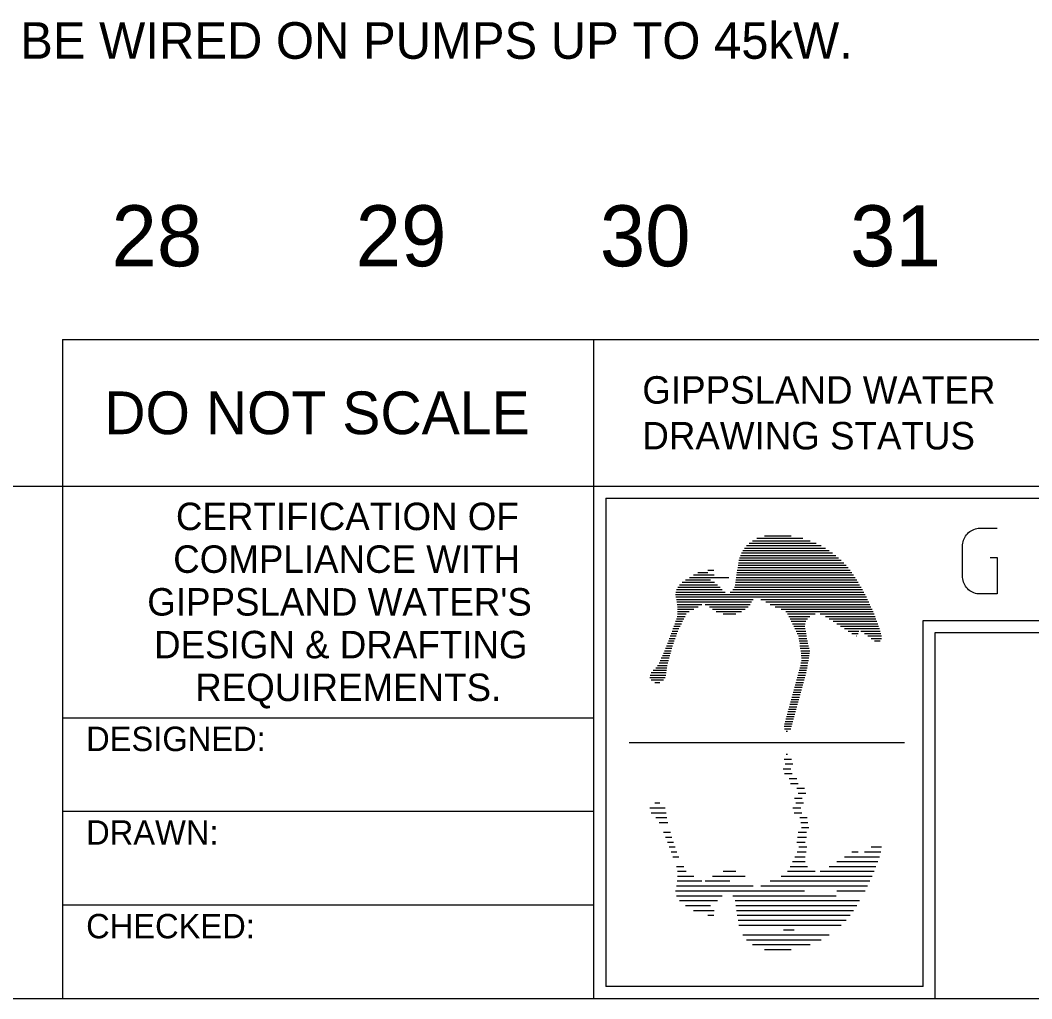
# Model space of a CAD drawing. Extents: x 0 to 841, y 0 to 594.
# Drawn here: x 589 to 671.9, y 15 to 95.2 of the extents above; entities that cross this region are included whole.
import ezdxf

# ---------------------------------------------------------------- set-up
doc = ezdxf.new("R2010")
doc.units = 0
doc.layers.add('A1BORDER', color=7, linetype='Continuous')
doc.layers.add('Level 1', color=7, linetype='Continuous')

msp = doc.modelspace()

# ---------------------------------------------------------------- linework, layer by layer
at = {"layer": 'A1BORDER'}
for p, q in [((592.5, 69), (592.5, 15)), ((592.5, 69), (829, 69)), ((636, 69), (636, 15)), ((28, 57), (829, 57)), ((637, 56), (788, 56)), ((637, 56), (637, 16)), ((648.74, 52.32), (654.24, 52.32)), ((649.02, 52.52), (653.76, 52.52)), ((649.39, 52.72), (653.15, 52.72)), ((650.01, 52.92), (652.2, 52.92)), ((648.12, 51.52), (655.59, 51.52)), ((648.23, 51.72), (655.31, 51.72)), ((648.37, 51.92), (655, 51.92)), ((648.53, 52.12), (654.64, 52.12)), ((647.88, 50.72), (656.5, 50.72)), ((647.91, 50.92), (656.3, 50.92)), ((647.96, 51.12), (656.08, 51.12)), ((648.03, 51.32), (655.85, 51.32)), ((644.18, 49.72), (645.89, 49.72)), ((644.54, 49.92), (645.36, 49.92)), ((645.37, 50.12), (645.86, 50.12)), ((647.71, 49.72), (657.31, 49.72)), ((647.75, 49.92), (657.17, 49.92)), ((647.78, 50.12), (657.02, 50.12)), ((647.81, 50.32), (656.86, 50.32)), ((647.85, 50.52), (656.69, 50.52)), ((643.04, 48.92), (646.16, 48.92)), ((643.26, 49.12), (645.9, 49.12)), ((643.54, 49.32), (645.57, 49.32)), ((643.85, 49.52), (647.09, 49.52)), ((647.61, 48.92), (657.8, 48.92)), ((647.63, 49.12), (657.68, 49.12)), ((647.66, 49.32), (657.57, 49.32)), ((647.69, 49.52), (657.44, 49.52)), ((642.73, 48.12), (658.25, 48.12)), ((642.75, 48.32), (646.79, 48.32)), ((642.81, 48.52), (646.55, 48.52)), ((642.9, 48.72), (646.37, 48.72)), ((647.19, 48.32), (658.14, 48.32)), ((647.42, 48.52), (658.03, 48.52)), ((647.54, 48.72), (657.92, 48.72)), ((642.74, 47.92), (658.35, 47.92)), ((642.79, 47.72), (649.08, 47.72)), ((642.83, 47.52), (648.95, 47.52)), ((642.85, 47.31), (644.88, 47.31)), ((645.14, 47.31), (648.83, 47.31)), ((649.72, 47.72), (658.45, 47.72)), ((650.12, 47.52), (658.55, 47.52)), ((650.48, 47.31), (658.64, 47.31)), ((642.87, 47.12), (644.57, 47.12)), ((642.87, 46.52), (643.6, 46.52)), ((642.88, 46.92), (644.23, 46.92)), ((642.88, 46.72), (643.83, 46.72)), ((645.49, 47.12), (648.67, 47.12)), ((645.76, 46.92), (648.42, 46.92)), ((646.05, 46.72), (648.11, 46.72)), ((646.62, 46.52), (647.67, 46.52)), ((650.87, 47.12), (658.73, 47.12)), ((651.36, 46.92), (658.82, 46.92)), ((651.76, 46.72), (658.9, 46.72)), ((651.88, 46.52), (654.15, 46.52)), ((654.57, 46.52), (658.99, 46.52)), ((642.65, 45.72), (643.2, 45.72)), ((642.72, 45.92), (643.3, 45.92)), ((642.79, 46.12), (643.4, 46.12)), ((642.84, 46.32), (643.5, 46.32)), ((651.99, 46.32), (653.71, 46.32)), ((652.1, 46.12), (653.52, 46.12)), ((652.2, 45.92), (653.4, 45.92)), ((652.31, 45.72), (653.33, 45.72)), ((655, 46.32), (659.07, 46.32)), ((655.31, 46.12), (659.14, 46.12)), ((655.62, 45.92), (659.22, 45.92)), ((655.93, 45.72), (659.29, 45.72)), ((663, 46), (788, 46)), ((663, 16), (663, 46)), ((642.35, 44.92), (642.83, 44.92)), ((642.43, 45.12), (642.9, 45.12)), ((642.5, 45.32), (643, 45.32)), ((642.57, 45.52), (643.1, 45.52)), ((652.41, 45.52), (653.31, 45.52)), ((652.5, 45.32), (653.34, 45.32)), ((652.6, 45.12), (653.38, 45.12)), ((652.69, 44.92), (653.41, 44.92)), ((656.24, 45.52), (659.35, 45.52)), ((656.55, 45.32), (659.42, 45.32)), ((656.86, 45.12), (657.74, 45.12)), ((657.17, 44.92), (657.68, 44.92)), ((657.91, 45.12), (659.48, 45.12)), ((658.19, 44.92), (659.54, 44.92)), ((664, 45), (829, 45)), ((664, 15), (664, 45)), ((641.99, 43.92), (642.48, 43.92)), ((642.06, 44.12), (642.55, 44.12)), ((642.13, 44.32), (642.62, 44.32)), ((642.21, 44.52), (642.69, 44.52)), ((642.28, 44.72), (642.76, 44.72)), ((652.78, 44.72), (653.44, 44.72)), ((652.83, 44.52), (653.48, 44.52)), ((652.86, 44.32), (653.53, 44.32)), ((652.89, 44.12), (653.57, 44.12)), ((652.91, 43.92), (653.62, 43.92)), ((657.51, 44.72), (657.54, 44.72)), ((658.47, 44.72), (659.59, 44.72)), ((658.75, 44.52), (659.58, 44.52)), ((659.02, 44.32), (659.47, 44.32)), ((641.64, 43.12), (642.25, 43.12)), ((641.73, 43.32), (642.3, 43.32)), ((641.82, 43.51), (642.35, 43.51)), ((641.91, 43.72), (642.41, 43.72)), ((652.94, 43.72), (653.67, 43.72)), ((652.97, 43.51), (653.71, 43.51)), ((653, 43.32), (653.69, 43.32)), ((653.02, 43.12), (653.67, 43.12)), ((641.25, 42.31), (642.04, 42.31)), ((641.37, 42.52), (642.09, 42.52)), ((641.46, 42.72), (642.15, 42.72)), ((641.55, 42.92), (642.2, 42.92)), ((652.95, 42.31), (653.53, 42.31)), ((652.99, 42.52), (653.57, 42.52)), ((653.03, 42.72), (653.61, 42.72)), ((653.05, 42.92), (653.64, 42.92)), ((640.63, 41.52), (641.93, 41.52)), ((640.73, 41.72), (641.95, 41.72)), ((640.9, 41.92), (641.97, 41.92)), ((641.1, 42.12), (642, 42.12)), ((652.74, 41.52), (653.37, 41.52)), ((652.79, 41.72), (653.41, 41.72)), ((652.85, 41.92), (653.45, 41.92)), ((652.9, 42.12), (653.49, 42.12)), ((640.62, 41.32), (641.88, 41.32)), ((640.72, 41.12), (641.73, 41.12)), ((641.03, 40.92), (641.43, 40.92)), ((652.52, 40.72), (653.15, 40.72)), ((652.57, 40.92), (653.2, 40.92)), ((652.63, 41.12), (653.26, 41.12)), ((652.68, 41.32), (653.31, 41.32)), ((652.3, 39.92), (652.93, 39.92)), ((652.36, 40.12), (652.99, 40.12)), ((652.41, 40.32), (653.04, 40.32)), ((652.47, 40.52), (653.1, 40.52)), ((652.09, 39.12), (652.72, 39.12)), ((652.14, 39.32), (652.77, 39.32)), ((652.2, 39.52), (652.82, 39.52)), ((652.25, 39.72), (652.88, 39.72)), ((651.82, 38.12), (652.44, 38.12)), ((651.87, 38.32), (652.5, 38.32)), ((651.92, 38.52), (652.55, 38.52)), ((651.98, 38.72), (652.61, 38.72)), ((652.03, 38.92), (652.66, 38.92)), ((636, 38), (592.5, 38)), ((651.63, 37.32), (652.23, 37.32)), ((651.65, 37.52), (652.28, 37.52)), ((651.71, 37.72), (652.34, 37.72)), ((651.76, 37.92), (652.39, 37.92)), ((651.64, 37.12), (652.17, 37.12)), ((651.79, 36.92), (651.9, 36.92)), ((638.93, 35.98), (661.47, 35.98)), ((651.79, 35.04), (651.9, 35.04)), ((651.63, 34.64), (652.23, 34.64)), ((651.71, 34.24), (652.34, 34.24)), ((651.54, 33.84), (652.17, 33.84)), ((651.65, 33.44), (652.28, 33.44)), ((652.03, 33.04), (652.66, 33.04)), ((652.14, 32.64), (652.77, 32.64)), ((652.66, 32.24), (653.29, 32.24)), ((652.77, 31.84), (653.4, 31.84)), ((641.03, 31.04), (641.43, 31.04)), ((652.47, 31.44), (653.1, 31.44)), ((652.57, 31.04), (653.2, 31.04)), ((636, 30.34), (592.5, 30.34)), ((640.62, 30.64), (641.88, 30.64)), ((640.73, 30.24), (641.95, 30.24)), ((641.1, 29.84), (642, 29.84)), ((652.34, 30.64), (652.97, 30.64)), ((652.45, 30.24), (653.07, 30.24)), ((652.9, 29.84), (653.49, 29.84)), ((641.37, 29.44), (642.09, 29.44)), ((652.99, 29.44), (653.57, 29.44)), ((653.05, 29.04), (653.64, 29.04)), ((641.73, 28.64), (642.3, 28.64)), ((641.91, 28.24), (642.41, 28.24)), ((652.72, 28.24), (653.44, 28.24)), ((652.77, 28.64), (653.46, 28.64)), ((642.06, 27.84), (642.55, 27.84)), ((642.21, 27.44), (642.69, 27.44)), ((652.66, 27.84), (653.35, 27.84)), ((652.83, 27.44), (653.48, 27.44)), ((658.75, 27.44), (659.58, 27.44)), ((642.35, 27.04), (642.83, 27.04)), ((642.5, 26.64), (643, 26.64)), ((652.5, 26.64), (653.34, 26.64)), ((652.69, 27.04), (653.41, 27.04)), ((656.55, 26.64), (659.42, 26.64)), ((657.17, 27.04), (657.68, 27.04)), ((658.19, 27.04), (659.54, 27.04)), ((642.79, 25.84), (643.4, 25.84)), ((652.1, 25.84), (653.52, 25.84)), ((652.31, 26.24), (653.33, 26.24)), ((655.31, 25.84), (659.14, 25.84)), ((655.93, 26.24), (659.29, 26.24)), ((642.87, 25.44), (643.6, 25.44)), ((642.88, 25.04), (644.23, 25.04)), ((645.76, 25.04), (648.42, 25.04)), ((646.62, 25.44), (647.67, 25.44)), ((651.36, 25.04), (658.82, 25.04)), ((651.88, 25.44), (654.15, 25.44)), ((654.57, 25.44), (658.99, 25.44)), ((642.79, 24.24), (649.08, 24.24)), ((642.85, 24.65), (644.88, 24.65)), ((645.14, 24.65), (647.18, 24.65)), ((649.72, 24.24), (658.45, 24.24)), ((650.48, 24.65), (658.64, 24.65)), ((642.73, 23.84), (653.27, 23.84)), ((642.81, 23.44), (646.55, 23.44)), ((647.42, 23.44), (655.89, 23.44)), ((655.94, 23.84), (658.25, 23.84)), ((636, 22.67), (592.5, 22.67)), ((643.04, 23.04), (646.16, 23.04)), ((643.54, 22.64), (645.57, 22.64)), ((647.61, 23.04), (657.8, 23.04)), ((647.66, 22.64), (657.57, 22.64)), ((644.18, 22.24), (645.89, 22.24)), ((645.37, 21.84), (645.86, 21.84)), ((647.71, 22.24), (657.31, 22.24)), ((647.78, 21.84), (657.02, 21.84)), ((647.85, 21.44), (656.69, 21.44)), ((647.91, 21.04), (656.3, 21.04)), ((648.23, 20.24), (655.31, 20.24)), ((651.57, 20.64), (652.44, 20.64)), ((648.53, 19.84), (654.64, 19.84)), ((649.02, 19.44), (653.76, 19.44)), ((650.01, 19.04), (652.2, 19.04)), ((663, 16), (637, 16)), ((829, 15), (28, 15))]:
    msp.add_line(p, q, dxfattribs=at)
msp.add_lwpolyline([(668.49, 51.15), (669.06, 51.15), (669.06, 48.16), (667.64, 48.16), (667.51, 48.16), (667.39, 48.18), (667.28, 48.21), (667.15, 48.25), (667.04, 48.3), (666.93, 48.36), (666.82, 48.43), (666.73, 48.51), (666.64, 48.6), (666.55, 48.7), (666.48, 48.8), (666.41, 48.91), (666.35, 49.02), (666.31, 49.14), (666.27, 49.27), (666.24, 49.39), (666.22, 49.52), (666.22, 49.66), (666.22, 52.05), (666.22, 52.18), (666.24, 52.31), (666.27, 52.43), (666.31, 52.56), (666.35, 52.67), (666.41, 52.79), (666.48, 52.9), (666.55, 53), (666.64, 53.1), (666.73, 53.19), (666.82, 53.27), (666.93, 53.34), (667.04, 53.4), (667.15, 53.45), (667.28, 53.49), (667.39, 53.52), (667.51, 53.54), (667.64, 53.54), (669.06, 53.54)], dxfattribs=at)

# ---------------------------------------------------------------- texts
for s, height, p in [('GIPPSLAND WATER', 2.25, (640, 63.75)), ('DO NOT SCALE', 3.5, (595.922, 61.25)), ('DRAWING STATUS', 2.25, (640, 60)), ('CERTIFICATION OF', 2.25, (601.795, 53.39)), ('COMPLIANCE WITH', 2.25, (601.57, 49.89)), ("GIPPSLAND WATER'S", 2.25, (599.446, 46.39)), ('DESIGN & DRAFTING', 2.25, (600.004, 42.89)), ('REQUIREMENTS.', 2.25, (603.371, 39.39)), ('DESIGNED:', 2, (594.44, 35.29)), ('DRAWN:', 2, (594.44, 27.62)), ('CHECKED:', 2, (594.44, 19.95))]:
    msp.add_text(s, height=height, dxfattribs=at).set_placement(p)
at = {"layer": 'Level 1'}
for s, height, p in [('THERMISTORS ONLY TO BE WIRED ON PUMPS UP TO 45kW.', 3, (540, 92)), ('28', 5, (596.517, 75)), ('29', 5, (616.517, 75)), ('30', 5, (636.517, 75)), ('31', 5, (657.015, 75))]:
    msp.add_text(s, height=height, dxfattribs=at).set_placement(p)

doc.saveas('drawing.dxf')
